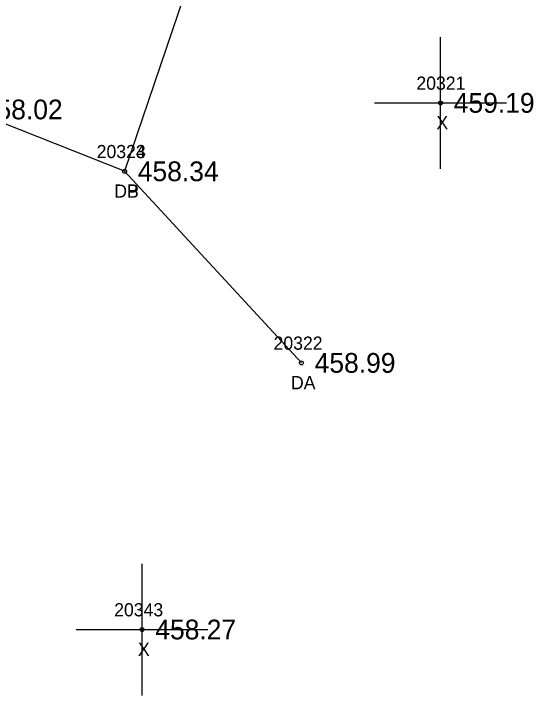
# Model space of a CAD drawing. Extents: x 1763022 to 1764007, y 824123 to 825394.
# Drawn here: x 1763369.7 to 1763409.1, y 824501.7 to 824553.5 of the extents above; entities that cross this region are included whole.
import ezdxf

# ---------------------------------------------------------------- set-up
doc = ezdxf.new("R2010")
doc.units = 0
for name, color, linetype in [('RD_EX_Driveway', 7, 'Continuous'), ('RD_EX_Driveway_txCode', 7, 'Continuous'), ('RD_EX_Misc', 7, 'Continuous'), ('RD_EX_Misc_txCode', 7, 'Continuous'), ('RD_EX_TX_Driveway_ELEV', 7, 'Continuous'), ('RD_EX_TX_Misc_ELEV', 7, 'Continuous'), ('RD_SMD_Locator', 7, 'Continuous')]:
    doc.layers.add(name, color=color, linetype=linetype)

msp = doc.modelspace()

# ---------------------------------------------------------------- linework, layer by layer
at = {"layer": 'RD_EX_Driveway'}
msp.add_line((1763391.514, 824526.954), (1763378.095, 824541.503), dxfattribs=at)
msp.add_lwpolyline([(1763364.489, 824579.397), (1763367.961, 824574.322), (1763373.628, 824569.514), (1763385.754, 824564.131), (1763378.095, 824541.503), (1763366.263, 824546.202), (1763360.488, 824545.692), (1763347.678, 824537.953)], dxfattribs=at)
at = {"layer": 'RD_EX_Misc'}
for p, q in [((1763402.065, 824541.698), (1763402.065, 824551.698)), ((1763397.065, 824546.698), (1763407.065, 824546.698)), ((1763379.423, 824501.706), (1763379.423, 824511.706)), ((1763374.423, 824506.706), (1763384.423, 824506.706))]:
    msp.add_line(p, q, dxfattribs=at)
at = {"layer": 'RD_SMD_Locator'}
for centre in [(1763402.065, 824546.698), (1763378.095, 824541.503), (1763378.095, 824541.503), (1763391.514, 824526.954), (1763379.423, 824506.706)]:
    msp.add_circle(centre, 0.15, dxfattribs=at)

# ---------------------------------------------------------------- texts
at = {"layer": 'RD_EX_Driveway_txCode'}
for s, p in [('20323', (1763375.977, 824542.503)), ('20324', (1763375.977, 824542.503)), ('DB', (1763377.315, 824539.503)), ('DP', (1763377.315, 824539.503)), ('20322', (1763389.396, 824527.954)), ('DA', (1763390.719, 824524.954))]:
    msp.add_text(s, height=1, dxfattribs=at).set_placement(p)
at = {"layer": 'RD_EX_Misc_txCode'}
for s, p in [('20321', (1763400.231, 824547.698)), ('X', (1763401.75, 824544.698)), ('20343', (1763377.305, 824507.706)), ('X', (1763379.108, 824504.706))]:
    msp.add_text(s, height=1, dxfattribs=at).set_placement(p)
at = {"layer": 'RD_EX_TX_Driveway_ELEV'}
for s, p in [('458.02', (1763367.263, 824545.452)), ('458.34', (1763379.095, 824540.753)), ('458.34', (1763379.095, 824540.753)), ('458.99', (1763392.514, 824526.204))]:
    msp.add_text(s, height=1.5, dxfattribs=at).set_placement(p)
at = {"layer": 'RD_EX_TX_Misc_ELEV'}
for s, p in [('459.19', (1763403.065, 824545.948)), ('458.27', (1763380.423, 824505.956))]:
    msp.add_text(s, height=1.5, dxfattribs=at).set_placement(p)

doc.saveas('drawing.dxf')
